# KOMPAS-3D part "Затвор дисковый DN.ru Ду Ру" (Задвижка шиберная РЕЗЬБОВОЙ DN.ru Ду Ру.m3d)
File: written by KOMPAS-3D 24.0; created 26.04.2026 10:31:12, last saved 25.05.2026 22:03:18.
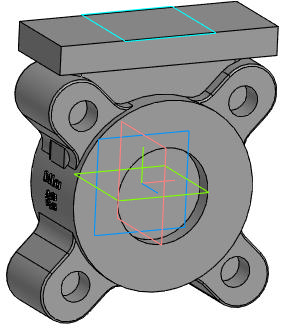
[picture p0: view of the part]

Document properties: Автор: R2D2; Полное имя файла: E:\Работа\Зайцев\GVKR1331M-1W-Fb-2P Задвижка шиберная с выдвижным штоком DN.ru Ду50-300 Ру16-10-6 с пневмоприводом\исходные материалы\DN50\Задвижка шиберная РЕЗЬБОВОЙ DN.ru Ду Ру.m3d

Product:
- Part/product: Затвор дисковый DN.ru Ду Ру
    Масса: 18.2
    Раздел спецификации: Прочие изделия
    Примечание: D050-23732

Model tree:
1. Смещенная плоскость:2
2. Диск
3. Корпус
4. Элемент выдавливания:3
     Расстояние 1 = 30
5. Элемент вращения:1
     Угол 1 = 360
6. Корпус штока
7. Элемент выдавливания:6  (with: Грань.Элемент вращения:1)
     Расстояние 1 = 82.5
8. Ушко  (with: Ребро.Элемент вращения:1)
9. Элемент выдавливания:5
10. Скругление:7  (with: Ребро.Элемент выдавливания:5)
     Радиус = 1
11. Эскиз:1  (with: Ребро.Элемент выдавливания:5)
12. Элемент выдавливания:12
     Расстояние 1 = 24; Расстояние 2 = 24
13. Элемент выдавливания:13
14. Массив по концентрической сетке:3  (with: Элемент выдавливания:5, Скругление:7, Элемент выдавливания:12, Элемент выдавливания:13)  (4 pattern instances)
     Шаг 2 = 360
15. Эскиз:2  (labels: Ребро.Элемент выдавливания:5.Экземпляр ( 1, 2 ); Ребро.Элемент выдавливания:5.Экземпляр ( 1, 3 ))
16. Элемент выдавливания:14
17. Эскиз:3  (with: Грань.Элемент выдавливания:6)
18. Элемент выдавливания:15
     Расстояние 2 = 15
19. Скругление:10  (with: Ребро.Элемент выдавливания:6)
     Радиус = 5
20. Эскиз:4  (labels: Задвижка шиберная с выдвижным штоком DN.ru Ду50 Ру16; Затвор дисковый DN.ru Ду200 Ру16)
21. Элемент выдавливания:16  (with: Грань.Элемент вращения:1)
     Расстояние 1 = 50.5; Смещение 1 = 1
22. Эскиз:5  (labels: Задвижка шиберная DN.ru Ду50 Ру10; Затвор дисковый DN.ru Ду200 Ру16)
23. Элемент выдавливания:17  (with: Грань.Элемент вращения:1)
     Расстояние 1 = 50.4969; Смещение 1 = 1
24. Скругление:8  (with: Ребро.Элемент вращения:1)
     Радиус = 1
25. ЛЕЙБЛ
26. Элемент выдавливания:11  (with: Грань.Элемент выдавливания:6)
     Расстояние 1 = 13.5; Смещение 1 = 1

Expressions: 360/n; d/2+20; c-8-2*t; v1301/2; dd/2
Referenced files in E:\Работа\Зайцев\GVKR1331E-1W-Fb-2P Задвижка шиберная DN.ru Ду50-300 Ру16-10-6\исходные материалы\DN50\: GVKR1331E-1W-Fb-2P Задвижка шиберная с выдвижным штоком DN.ru Ду50 Ру16.a3d, GVKR1331E-1W-Fb-2P Задвижка шиберная DN.ru Ду50 Ру16.a3d
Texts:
  Угловой размер с обрывом
  GOST 26.020 Pr3
  var3D
  ширина затвора по металлу
  Диаметр исо фланца
  id4
  Диуметр отверстия  исо фланца
  id3
  ось отв. исо фланца
  DN+10
  dk-4
  Плоскость ZY.Начало координат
